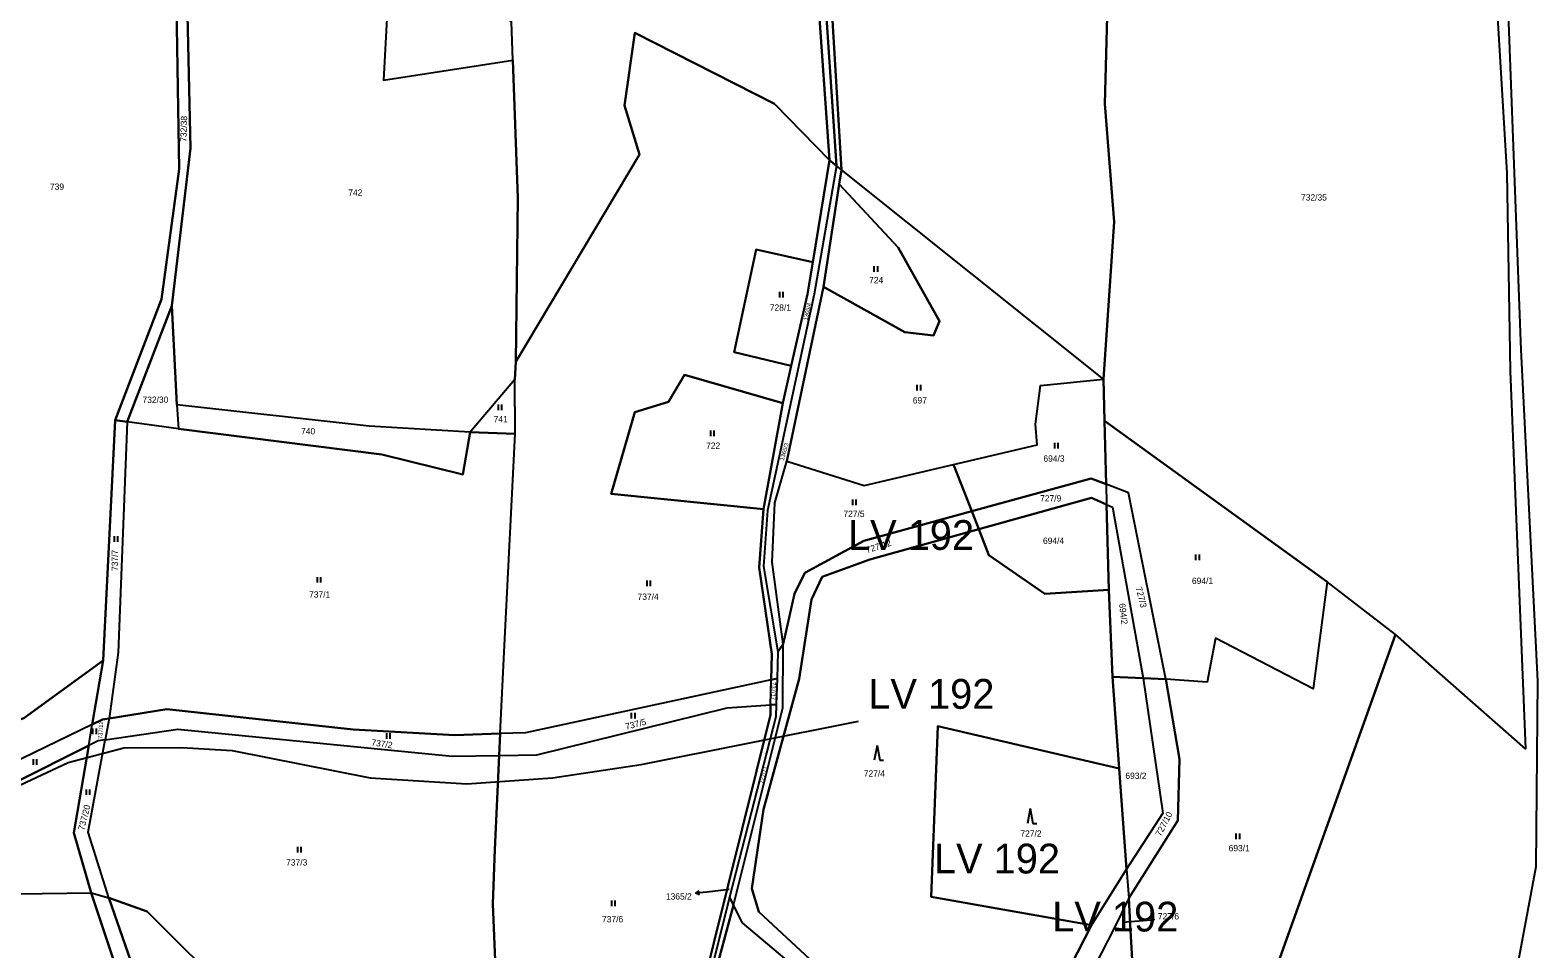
# Model space of a CAD drawing. Extents: x -588699 to -585793, y -1060280 to -1056731.
# Drawn here: x -587129.7 to -586724.4, y -1057998.4 to -1057751.4 of the extents above; entities that cross this region are included whole.
import ezdxf

# ---------------------------------------------------------------- set-up
doc = ezdxf.new("R2010")
doc.units = 0
for name, color, linetype in [('Druh pozemku', 7, 'Continuous'), ('Parcela nároku', 7, 'Continuous'), ('Parcelní číslo', 7, 'Continuous'), ('Vnější obvod_k šeření', 7, 'Continuous'), ('Vnější obvod_převzatý', 7, 'Continuous')]:
    doc.layers.add(name, color=color, linetype=linetype)

msp = doc.modelspace()

# ---------------------------------------------------------------- linework, layer by layer
at = {"layer": 'Druh pozemku'}
for p, q in [((-586902.85, -1057814.88), (-586902.85, -1057816.38)), ((-586901.83, -1057816.38), (-586901.83, -1057814.88)), ((-586928.29, -1057821.76), (-586928.29, -1057823.26)), ((-586927.27, -1057823.26), (-586927.27, -1057821.76)), ((-586891.31, -1057846.78), (-586891.31, -1057848.28)), ((-586890.29, -1057848.28), (-586890.29, -1057846.78)), ((-587003.9, -1057852.03), (-587003.9, -1057853.53)), ((-587002.88, -1057853.53), (-587002.88, -1057852.03)), ((-586946.84, -1057859), (-586946.84, -1057860.5)), ((-586945.82, -1057860.5), (-586945.82, -1057859)), ((-586854.35, -1057862.31), (-586854.35, -1057863.81)), ((-586853.33, -1057863.81), (-586853.33, -1057862.31)), ((-586908.65, -1057877.61), (-586908.65, -1057879.11)), ((-586907.62, -1057879.11), (-586907.62, -1057877.61)), ((-587107.16, -1057887.42), (-587107.16, -1057888.92)), ((-587106.14, -1057888.92), (-587106.14, -1057887.42)), ((-586816.38, -1057892.37), (-586816.38, -1057893.87)), ((-586815.35, -1057893.87), (-586815.35, -1057892.37)), ((-587052.59, -1057898.42), (-587052.59, -1057899.92)), ((-587051.57, -1057899.92), (-587051.57, -1057898.42)), ((-586963.96, -1057899.34), (-586963.96, -1057900.84)), ((-586962.94, -1057900.84), (-586962.94, -1057899.34)), ((-586968.09, -1057934.91), (-586968.09, -1057936.41)), ((-586967.07, -1057936.41), (-586967.07, -1057934.91)), ((-587112.93, -1057939.17), (-587112.93, -1057940.67)), ((-587111.91, -1057940.67), (-587111.91, -1057939.17)), ((-587033.95, -1057940.4), (-587033.95, -1057941.9)), ((-587032.93, -1057941.9), (-587032.93, -1057940.4)), ((-586902.04, -1057943.68), (-586902.78, -1057947.68)), ((-586902.04, -1057943.68), (-586901.31, -1057947.68)), ((-587128.95, -1057947.39), (-587128.95, -1057948.89)), ((-587127.93, -1057948.89), (-587127.93, -1057947.39)), ((-586901.31, -1057947.68), (-586900.31, -1057947.68)), ((-587114.67, -1057955.49), (-587114.67, -1057956.99)), ((-587113.65, -1057956.99), (-587113.65, -1057955.49)), ((-586860.84, -1057960.65), (-586861.58, -1057964.65)), ((-586860.84, -1057960.65), (-586860.11, -1057964.65)), ((-586860.11, -1057964.65), (-586859.11, -1057964.65)), ((-586805.55, -1057967.35), (-586805.55, -1057968.85)), ((-586804.53, -1057968.85), (-586804.53, -1057967.35)), ((-587057.84, -1057970.98), (-587057.84, -1057972.48)), ((-587056.82, -1057972.48), (-587056.82, -1057970.98)), ((-586973.44, -1057985.37), (-586973.44, -1057986.87)), ((-586972.42, -1057986.87), (-586972.42, -1057985.37))]:
    msp.add_line(p, q, dxfattribs=at)
at = {"layer": 'Parcela nároku'}
for points in [[(-587105.26, -1057680.3), (-587092.55, -1057679.16), (-587091.45, -1057679.28), (-587089.66, -1057788.78), (-587094.44, -1057823.73), (-587106.88, -1057856.27), (-587110.11, -1057920.88), (-587131.45, -1057936.32), (-587153.9, -1057943.43), (-587157.66, -1057936.51), (-587160.04, -1057884.63), (-587160.43, -1057808.36), (-587163.92, -1057746.79), (-587163.78, -1057671.48), (-587135.86, -1057679.58)], [(-587094.44, -1057823.73), (-587089.66, -1057788.78), (-587091.45, -1057679.28), (-587088.98, -1057679.55), (-587086.62, -1057783.15), (-587091.62, -1057825.5), (-587103.6, -1057856.71), (-587106.88, -1057856.27)], [(-586999.95, -1057759.45), (-586998.64, -1057796.43), (-586999.15, -1057840.56), (-586999.43, -1057845.28), (-587011.44, -1057859.42), (-587038.6, -1057857.88), (-587090.32, -1057852.16), (-587091.62, -1057825.5), (-587086.62, -1057783.15), (-587088.98, -1057679.55), (-587064.02, -1057682.31), (-587064.02, -1057687.17), (-587080.66, -1057684.93), (-587081.55, -1057694.09), (-587075.41, -1057694.88), (-587071.5, -1057708.51), (-587033.3, -1057738.24), (-587034.75, -1057764.83)], [(-587061.71, -1057682.56), (-587064.02, -1057682.31), (-587064.02, -1057687.17), (-587080.66, -1057684.93), (-587081.55, -1057694.09), (-587075.41, -1057694.88), (-587071.5, -1057708.51), (-587033.3, -1057738.24), (-587034.75, -1057764.83), (-586999.95, -1057759.45), (-587000.32, -1057749.13), (-587020.15, -1057732.87), (-587016.99, -1057727.62)], [(-586917.51, -1057690.63), (-586875.17, -1057686.51), (-586832.88, -1057689.84), (-586839.67, -1057730.75), (-586840.75, -1057771.16), (-586838.29, -1057802.9), (-586841.17, -1057845.18), (-586911.61, -1057788.9)], [(-586998.28, -1057687.83), (-586959.32, -1057692.37), (-586921.53, -1057690.8), (-586914.78, -1057786.32), (-586929.59, -1057771.15), (-586967.19, -1057752.11), (-586969.96, -1057771.61), (-586965.89, -1057784.83), (-586999.15, -1057840.56), (-586998.64, -1057796.43), (-586999.95, -1057759.45), (-587000.32, -1057749.13), (-587000.74, -1057737.12)], [(-586921.53, -1057690.8), (-586919.43, -1057690.71), (-586912.96, -1057787.82), (-586914.78, -1057786.32)], [(-586919.43, -1057690.71), (-586917.51, -1057690.63), (-586911.61, -1057788.9), (-586912.96, -1057787.82)], [(-586839.67, -1057730.75), (-586832.88, -1057689.84), (-586737.76, -1057705.88), (-586732.75, -1057789.84), (-586731.77, -1057843.03), (-586727.68, -1057944.56), (-586762.68, -1057913.84), (-586781.03, -1057899.72), (-586840.9, -1057856.46), (-586841.17, -1057845.18), (-586838.29, -1057802.9), (-586840.75, -1057771.16)], [(-586999.43, -1057845.28), (-586999.15, -1057840.56), (-586965.89, -1057784.83), (-586969.96, -1057771.61), (-586967.19, -1057752.11), (-586929.59, -1057771.15), (-586914.78, -1057786.32), (-586919.26, -1057813.78), (-586934.56, -1057810.4), (-586940.48, -1057838), (-586925.1, -1057841.64), (-586927.37, -1057851.65), (-586953.77, -1057844.06), (-586958.13, -1057851.33), (-586967.17, -1057854.12), (-586973.54, -1057876.02), (-586932.59, -1057880.16), (-586933.74, -1057895.83), (-586930.33, -1057919.12), (-586930.48, -1057926.03), (-586996.55, -1057940.31), (-587003.32, -1057940.51), (-587002.1, -1057914.96), (-586999.34, -1057859.94)], [(-586927.37, -1057851.65), (-586925.1, -1057841.64), (-586920.72, -1057822.35), (-586919.26, -1057813.78), (-586914.78, -1057786.32), (-586912.96, -1057787.82), (-586918.89, -1057822.39), (-586931.51, -1057880.48), (-586932.56, -1057895.6), (-586928.68, -1057918.48), (-586928.91, -1057925.69), (-586930.48, -1057926.03), (-586930.33, -1057919.12), (-586933.74, -1057895.83), (-586932.59, -1057880.16)], [(-586931.51, -1057880.48), (-586932.56, -1057895.6), (-586928.68, -1057918.48), (-586927.28, -1057916.44), (-586930.23, -1057894.45), (-586929.49, -1057878.46), (-586926.32, -1057867.22), (-586916.46, -1057820.39), (-586912.21, -1057792.8), (-586911.61, -1057788.9), (-586912.96, -1057787.82), (-586918.89, -1057822.39)], [(-586859, -1057862.84), (-586859.47, -1057857.29), (-586858.06, -1057846.88), (-586841.17, -1057845.18), (-586911.61, -1057788.9), (-586912.21, -1057792.8), (-586896.32, -1057809.8), (-586885.24, -1057829.58), (-586886.81, -1057833.46), (-586894.57, -1057832.54), (-586916.46, -1057820.39), (-586926.32, -1057867.22), (-586905.47, -1057873.84), (-586881.46, -1057868.16)], [(-586912.21, -1057792.8), (-586916.46, -1057820.39), (-586894.57, -1057832.54), (-586886.81, -1057833.46), (-586885.24, -1057829.58), (-586896.32, -1057809.8)], [(-586940.48, -1057838), (-586934.56, -1057810.4), (-586919.26, -1057813.78), (-586920.72, -1057822.35), (-586925.1, -1057841.64)], [(-587091.62, -1057825.5), (-587090.32, -1057852.16), (-587089.84, -1057858.54), (-587103.6, -1057856.71)], [(-586953.77, -1057844.06), (-586927.37, -1057851.65), (-586932.59, -1057880.16), (-586973.54, -1057876.02), (-586967.17, -1057854.12), (-586958.13, -1057851.33)], [(-586999.34, -1057859.94), (-586999.43, -1057845.28), (-587011.44, -1057859.42)], [(-586841.17, -1057845.18), (-586840.9, -1057856.46), (-586840.45, -1057873.43), (-586844.45, -1057871.88), (-586876.57, -1057880.73), (-586881.46, -1057868.16), (-586859, -1057862.84), (-586859.47, -1057857.29), (-586858.06, -1057846.88)], [(-587011.44, -1057859.42), (-587038.6, -1057857.88), (-587090.32, -1057852.16), (-587089.84, -1057858.54), (-587035.21, -1057865.5), (-587013.38, -1057870.88)], [(-587110.11, -1057920.88), (-587106.88, -1057856.27), (-587103.6, -1057856.71), (-587106.04, -1057918.7), (-587108.51, -1057936.43), (-587110.31, -1057936.72), (-587113.02, -1057938.03)], [(-587106.04, -1057918.7), (-587108.51, -1057936.43), (-587092.94, -1057933.94), (-587042.87, -1057939.4), (-587015.52, -1057940.88), (-587003.32, -1057940.51), (-587002.1, -1057914.96), (-586999.34, -1057859.94), (-587011.44, -1057859.42), (-587013.38, -1057870.88), (-587035.21, -1057865.5), (-587089.84, -1057858.54), (-587103.6, -1057856.71)], [(-586840.9, -1057856.46), (-586781.03, -1057899.72), (-586784.82, -1057928.46), (-586811.05, -1057914.87), (-586813.27, -1057926.7), (-586824.36, -1057925.87), (-586834.42, -1057875.77), (-586840.45, -1057873.43)], [(-586929.49, -1057878.46), (-586926.32, -1057867.22), (-586905.47, -1057873.84), (-586881.46, -1057868.16), (-586876.57, -1057880.73), (-586905.56, -1057888.71), (-586921.41, -1057897.28), (-586924.24, -1057902.95), (-586927.28, -1057916.44), (-586930.23, -1057894.45)], [(-586876.57, -1057880.73), (-586844.45, -1057871.88), (-586840.45, -1057873.43), (-586840.31, -1057878.9), (-586844.35, -1057877.16), (-586874.69, -1057885.55)], [(-586874.69, -1057885.55), (-586844.35, -1057877.16), (-586840.31, -1057878.9), (-586839.71, -1057901.81), (-586856.89, -1057902.92), (-586871.95, -1057892.57)], [(-586824.36, -1057925.87), (-586834.42, -1057875.77), (-586840.45, -1057873.43), (-586840.31, -1057878.9), (-586838.69, -1057879.59), (-586830.45, -1057925.58)], [(-586840.31, -1057878.9), (-586838.69, -1057879.59), (-586830.45, -1057925.58), (-586838.69, -1057925.2), (-586839.71, -1057901.81)], [(-586932.54, -1057960.91), (-586922.94, -1057925.79), (-586919.61, -1057904.44), (-586916.78, -1057898.35), (-586904.01, -1057893.66), (-586874.69, -1057885.55), (-586871.95, -1057892.57), (-586856.89, -1057902.92), (-586839.71, -1057901.81), (-586838.69, -1057925.2), (-586836.9, -1057949.89), (-586885.72, -1057938.48), (-586887.5, -1057984.42), (-586844.33, -1057992.02), (-586857.53, -1058017.76), (-586869.72, -1058025.52), (-586880.07, -1058024.23), (-586920.07, -1058001.12), (-586933.84, -1057988.46), (-586935.69, -1057982.17)], [(-586820.69, -1057947.35), (-586821.14, -1057963.83), (-586834.37, -1057984.74), (-586833.87, -1057993.43), (-586831.56, -1058034.01), (-586831.56, -1058054.99), (-586817.52, -1058043.81), (-586799.51, -1058016.91), (-586762.68, -1057913.84), (-586781.03, -1057899.72), (-586784.82, -1057928.46), (-586811.05, -1057914.87), (-586813.27, -1057926.7), (-586824.36, -1057925.87)], [(-586927.28, -1057916.44), (-586928.68, -1057918.48), (-586928.91, -1057925.69), (-586929.13, -1057932.68), (-586929.24, -1057935.95), (-586941.73, -1057984.43), (-586940.62, -1057986.63), (-586927.33, -1057933.58)], [(-587154.07, -1057957.94), (-587153.9, -1057943.43), (-587131.45, -1057936.32), (-587110.11, -1057920.88), (-587113.02, -1057938.03)], [(-587003.32, -1057940.51), (-587003.6, -1057946.39), (-586993.53, -1057946.23), (-586942.28, -1057933.57), (-586930.63, -1057932.8), (-586930.48, -1057926.03), (-586996.55, -1057940.31)], [(-586930.63, -1057932.8), (-586930.48, -1057926.03), (-586928.91, -1057925.69), (-586929.13, -1057932.68)], [(-586830.45, -1057925.58), (-586825.23, -1057961.89), (-586834.94, -1057976.91), (-586836.9, -1057949.89), (-586838.69, -1057925.2)], [(-586824.36, -1057925.87), (-586830.45, -1057925.58), (-586825.23, -1057961.89), (-586834.94, -1057976.91), (-586834.37, -1057984.74), (-586821.14, -1057963.83), (-586820.69, -1057947.35)], [(-587042.87, -1057939.4), (-587092.94, -1057933.94), (-587108.51, -1057936.43), (-587109.56, -1057942.16), (-587090.06, -1057939.29), (-587016.24, -1057946.59), (-587003.6, -1057946.39), (-587003.32, -1057940.51), (-587015.52, -1057940.88)], [(-586942.28, -1057933.57), (-586930.63, -1057932.8), (-586930.69, -1057935.48), (-586949.68, -1058011.92), (-586949.36, -1058032.9), (-586968.51, -1058017.77), (-586993.14, -1058015.42), (-587004.74, -1058039.37), (-587012.03, -1058037.53), (-587004.6, -1058003.69), (-587005.35, -1057986.23), (-587004.81, -1057971.63), (-587003.6, -1057946.39), (-586993.53, -1057946.23)], [(-586930.63, -1057932.8), (-586929.13, -1057932.68), (-586929.24, -1057935.95), (-586941.73, -1057984.43), (-586948.78, -1058012.87), (-586947.43, -1058034.44), (-586949.36, -1058032.9), (-586949.68, -1058011.92), (-586930.69, -1057935.48)], [(-587113.02, -1057938.03), (-587154.07, -1057957.94), (-587154.14, -1057963.9), (-587113.98, -1057943.72)], [(-587113.98, -1057943.72), (-587113.02, -1057938.03), (-587110.31, -1057936.72), (-587108.51, -1057936.43), (-587109.56, -1057942.16), (-587111.4, -1057942.43)], [(-587108.57, -1057984.69), (-587114.13, -1057967.04), (-587109.56, -1057942.16), (-587111.4, -1057942.43), (-587113.98, -1057943.72), (-587117.94, -1057967.14), (-587113.33, -1057983.29)], [(-587005.35, -1057986.23), (-587004.6, -1058003.69), (-587012.03, -1058037.53), (-587055.22, -1058026.64), (-587074.72, -1058011.8), (-587098.26, -1057988.35), (-587108.57, -1057984.69), (-587114.13, -1057967.04), (-587109.56, -1057942.16), (-587090.06, -1057939.29), (-587016.24, -1057946.59), (-587003.6, -1057946.39), (-587004.81, -1057971.63)], [(-586887.5, -1057984.42), (-586885.72, -1057938.48), (-586836.9, -1057949.89), (-586834.94, -1057976.91), (-586844.33, -1057992.02)], [(-587113.33, -1057983.29), (-587117.94, -1057967.14), (-587113.98, -1057943.72), (-587154.14, -1057963.9), (-587154.26, -1057974.05), (-587154.26, -1057976.54), (-587133.01, -1057983.57)], [(-587093.47, -1058042.85), (-587083.2, -1058085.63), (-587087.45, -1058131.23), (-587096.95, -1058176.54), (-587108.49, -1058212.36), (-587125.77, -1058278.15), (-587153.1, -1058357.53), (-587158, -1058368.22), (-587193.45, -1058428.69), (-587200.12, -1058424.25), (-587247.18, -1058391.8), (-587222.83, -1058325.23), (-587191.01, -1058241.74), (-587172.24, -1058142), (-587169.7, -1058107.61), (-587162.67, -1058067.38), (-587154.26, -1057976.54), (-587133.01, -1057983.57), (-587113.33, -1057983.29)], [(-587108.49, -1058212.36), (-587096.95, -1058176.54), (-587087.45, -1058131.23), (-587083.2, -1058085.63), (-587093.47, -1058042.85), (-587113.33, -1057983.29), (-587108.57, -1057984.69), (-587093.66, -1058027.53), (-587078.98, -1058086.47), (-587083.52, -1058130.86), (-587092.03, -1058176.89), (-587104.48, -1058214.01), (-587120.31, -1058276.98), (-587148.32, -1058357.26), (-587158.27, -1058377.37), (-587191.39, -1058430.39), (-587193.45, -1058428.69), (-587158, -1058368.22), (-587153.1, -1058357.53), (-587125.77, -1058278.15)], [(-586940.62, -1057986.63), (-586941.73, -1057984.43), (-586948.78, -1058012.87), (-586947.43, -1058034.44), (-586945.61, -1058035.89), (-586947.52, -1058012.27)], [(-586838.24, -1057992.79), (-586853.58, -1058022.63), (-586867.53, -1058031.14), (-586880.74, -1058029.19), (-586913.72, -1058012), (-586938.21, -1057991.39), (-586940.62, -1057986.63), (-586947.52, -1058012.27), (-586945.61, -1058035.89), (-586944.18, -1058047.87), (-586890.81, -1058068.59), (-586870.41, -1058063.91), (-586845.72, -1058038.51), (-586831.56, -1058034.01), (-586833.87, -1057993.43)], [(-586834.37, -1057984.74), (-586838.24, -1057992.79), (-586833.87, -1057993.43)]]:
    msp.add_lwpolyline(points, close=True, dxfattribs=at)
for points in [[(-586737.76, -1057705.88), (-586732.75, -1057789.84), (-586731.77, -1057843.03), (-586727.68, -1057944.56), (-586762.68, -1057913.84), (-586799.51, -1058016.91), (-586817.52, -1058043.81), (-586831.56, -1058054.99), (-586846.86, -1058152.34), (-586855.66, -1058231.54)], [(-586769.76, -1058238.68), (-586742.78, -1058072.26), (-586724.8, -1057976.24), (-586724.37, -1057926.35), (-586728.86, -1057837.37), (-586733.58, -1057711.23)], [(-586769.76, -1058238.68), (-586742.78, -1058072.26), (-586724.8, -1057976.24), (-586724.37, -1057926.35), (-586728.86, -1057837.37), (-586733.58, -1057711.23)], [(-586913.72, -1058012), (-586938.21, -1057991.39), (-586940.62, -1057986.63), (-586927.33, -1057933.58), (-586927.28, -1057916.44), (-586924.24, -1057902.95), (-586921.41, -1057897.28), (-586905.56, -1057888.71), (-586876.57, -1057880.73), (-586874.69, -1057885.55), (-586904.01, -1057893.66), (-586916.78, -1057898.35), (-586919.61, -1057904.44), (-586922.94, -1057925.79), (-586932.54, -1057960.91), (-586935.69, -1057982.17), (-586933.84, -1057988.46), (-586920.07, -1058001.12)], [(-586857.53, -1058017.76), (-586844.33, -1057992.02), (-586834.94, -1057976.91), (-586834.37, -1057984.74), (-586838.24, -1057992.79), (-586853.58, -1058022.63)], [(-587148.32, -1058357.26), (-587120.31, -1058276.98), (-587104.48, -1058214.01), (-587092.03, -1058176.89), (-587083.52, -1058130.86), (-587078.98, -1058086.47), (-587093.66, -1058027.53), (-587108.57, -1057984.69), (-587098.26, -1057988.35), (-587074.72, -1058011.8), (-587055.22, -1058026.64), (-587048.36, -1058039), (-587018.13, -1058067.3), (-587021.38, -1058110.94), (-587019.13, -1058132.51), (-587014.51, -1058157.25), (-587025.35, -1058230.42), (-587037.95, -1058281.07), (-587049.98, -1058316), (-587082.75, -1058391.16), (-587120.59, -1058488.29), (-587141.1, -1058482.75)]]:
    msp.add_lwpolyline(points, dxfattribs=at)
at = {"layer": 'Parcelní číslo'}
for p, q in [((-586941.82, -1057982.43), (-586947.79, -1057983.09)), ((-586947.79, -1057983.09), (-586950.77, -1057983.42)), ((-586836.03, -1057991.21), (-586830.52, -1057990.73)), ((-586830.52, -1057990.73), (-586827.53, -1057990.47))]:
    msp.add_line(p, q, dxfattribs=at)
for points in [[(-586949.72, -1057983.81), (-586950.77, -1057983.42), (-586949.83, -1057982.81)], [(-586828.57, -1057990.06), (-586827.53, -1057990.47), (-586828.48, -1057991.05)]]:
    msp.add_lwpolyline(points, dxfattribs=at)
at = {"layer": 'Vnější obvod_k šeření'}
msp.add_lwpolyline([(-587175.02, -1057974.24), (-587119.54, -1057948.26), (-587104.55, -1057944.37), (-587088.99, -1057944.2), (-587075.37, -1057945), (-587038.34, -1057952.41), (-587012.31, -1057954.01), (-586989.29, -1057952.41), (-586965.47, -1057948.8), (-586907.01, -1057937.19)], dxfattribs=at)

# ---------------------------------------------------------------- texts
at = {"layer": 'Parcela nároku'}
for s, height, rotation, p in [('732/38', 1.7, 88.3153, (-587087.69, -1057781.42)), ('1365/4', 1.14, 76.9559, (-586920.77, -1057829.54)), ('1365/3', 1.14, 73.9511, (-586927.11, -1057867.18)), ('727/12', 1.7, 17.1303, (-586904.69, -1057892)), ('737/7', 1.7, 90, (-587106.12, -1057896.78)), ('727/3', 1.7, 283.9529, (-586832.49, -1057901.28)), ('694/2', 1.7, 276.7797, (-586836.98, -1057905.58)), ('737/17', 1.14, 268.983, (-586930.35, -1057926.65)), ('737/12', 1.14, 87.7688, (-587110.28, -1057942.01)), ('737/5', 1.7, 14.3924, (-586969.47, -1057939.49)), ('737/2', 1.7, 351.8177, (-587038.06, -1057943.67)), ('727/11', 1.14, 76.917, (-586932.6, -1057954.1)), ('737/20', 1.7, 75.556, (-587115.22, -1057966.62)), ('727/10', 1.7, 62.4209, (-586825.76, -1057968.24))]:
    msp.add_text(s, height=height, rotation=rotation, dxfattribs=at).set_placement(p)
for s, height, p in [('739', 1.7, (-587124.4, -1057794.32)), ('742', 1.7, (-587044.2, -1057795.92)), ('732/35', 1.7, (-586788.04, -1057797.19)), ('724', 1.7, (-586904.15, -1057819.42)), ('728/1', 1.7, (-586930.86, -1057826.82)), ('732/30', 1.7, (-587099.52, -1057851.59)), ('697', 1.7, (-586892.41, -1057851.76)), ('741', 1.7, (-587005.11, -1057856.81)), ('740', 1.7, (-587056.88, -1057860.05)), ('722', 1.7, (-586947.99, -1057863.95)), ('694/3', 1.7, (-586857.3, -1057867.4)), ('727/9', 1.7, (-586858.19, -1057878.1)), ('727/5', 1.7, (-586911.07, -1057882.25)), ('694/4', 1.7, (-586857.42, -1057889.5)), ('694/1', 1.7, (-586817.37, -1057900.28)), ('737/1', 1.7, (-587054.73, -1057903.96)), ('737/4', 1.7, (-586966.42, -1057904.55)), ('727/4', 1.7, (-586905.59, -1057952.07)), ('693/2', 1.7, (-586835.27, -1057952.69)), ('727/2', 1.7, (-586863.49, -1057968.22)), ('693/1', 1.7, (-586807.5, -1057972.15)), ('737/3', 1.7, (-587060.9, -1057975.97)), ('1365/2', 0.1, (-586942.03, -1057982.43)), ('737/6', 1.7, (-586975.97, -1057991.25)), ('727/6', 0.1, (-586836.21, -1057991.21))]:
    msp.add_text(s, height=height, dxfattribs=at).set_placement(p)
at = {"layer": 'Parcelní číslo'}
for s, p in [('1365/2', (-586958.8, -1057985.12)), ('727/6', (-586826.53, -1057990.47))]:
    msp.add_text(s, height=1.7, dxfattribs=at).set_placement(p)
at = {"layer": 'Vnější obvod_převzatý'}
for p in [(-586909.85, -1057891.11), (-586904.38, -1057933.83), (-586886.74, -1057978.1), (-586854.93, -1057993.7)]:
    msp.add_text('LV 192', height=8, dxfattribs=at).set_placement(p)

doc.saveas('drawing.dxf')
